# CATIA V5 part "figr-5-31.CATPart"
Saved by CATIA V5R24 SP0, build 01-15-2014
Part number: Part1
Bounding box of the stored display mesh (mm): x -32.491 to 32.491, y -32.393 to 32.5, z 0 to 91.19
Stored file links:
  D:\KAVITA\CATIA V5-6R2014 Project_ Kavita\CATIA V5-6R2014_partfiles\Partfiles\c05_catia_v5-6r2014_prt\figr-5-31.CATPart
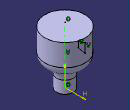
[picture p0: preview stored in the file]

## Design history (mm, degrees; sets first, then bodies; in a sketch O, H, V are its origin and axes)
Body1 (main body)
  Sketch1 on yz-plane, origin (0, 0, 0), H (0, 1, 0), V (0, 0, 1)
    axis line L1 (0, 0) -> (0, 100.0993)
    line L2 (0, 0) -> (13.3295, 0)
    line L3 (13.3295, 0) -> (13.3295, 19.6564)
    arc A1 centre (31.7623, 19.6564) radius 18.4328 from (13.3295, 19.6564) to (23.518, 36.1427) cw
    arc A2 centre (16.25, 50.6768) radius 16.25 from (23.518, 36.1427) to (32.5, 50.6768) ccw
    line L4 (32.5, 50.6768) -> (32.5, 85.6563)
    line L5 (32.5, 85.6563) -> (0, 85.6563)
    point P9 (0, 85.6563)
    line L6 (0, 85.6563) -> (0, 0)
    radius about axis L4 L1 = 32.5
    vertical: L1 V, L3 V, L4 V
    horizontal: L2 H, L5 H
    tangency: A1 L3, A2 L1, A2 A1, L4 A2, L6 A2
    coincidence: P9 L1
  Shaft1: profile Sketch1, axis Sketch1.L1, angle 360
  Sketch2 on yz-plane, origin (0, 0, 0), H (0, 1, 0), V (0, 0, 1)
    axis line L1 (0, 0) -> (0, 91.1904)
    point P1 (0, 0)
    point P2 (0, 91.1904)
    line L2 (32.5, 78.7512) -> (21.4593, 75.7196)
    line L3 (21.4593, 75.7196) -> (21.4593, 66.4534)
    line L4 (21.4593, 66.4534) -> (32.5, 63.9927)
    line L5 (32.5, 63.9927) -> (32.5, 78.7512)
    coincidence: P1 H, P2 V
    vertical: L1 V, L3 V, L5 V
  Groove1: profile Sketch2, axis Sketch2.L1, angle 360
